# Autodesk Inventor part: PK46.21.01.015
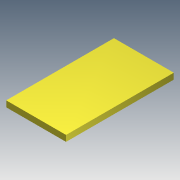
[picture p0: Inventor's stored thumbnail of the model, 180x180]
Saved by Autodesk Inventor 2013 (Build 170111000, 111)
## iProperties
Created: 2005-04
Part Number: PK46.21.01.015
Material: Steel, Mild
Document SubType Name: Modeling
Designer: salex
Manufacturer: Standard
Standards Organization: Custom
Density: 7.86 g/cm^3
Author: salex
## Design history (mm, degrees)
sketch "Эскиз1"
  geometry: L1 (0, 0)-(100, 0); L2 (100, 0)-(100, 180); L3 (100, 180)-(0, 180); L4 (0, 180)-(0, 0)
  constraints: 8 end point, 2 parallel, 1 horizontal, 1 perpendicular, 1 other
  dimensions: "d0" = 180 distance of L3.end L1.start; "d1" = 100 distance of L1.start L1.end
extrude "Выдавливание1" new body sketch "Эскиз1" distance "d2" = 10; taper "d3" = 0 deg
body "Solid1"
